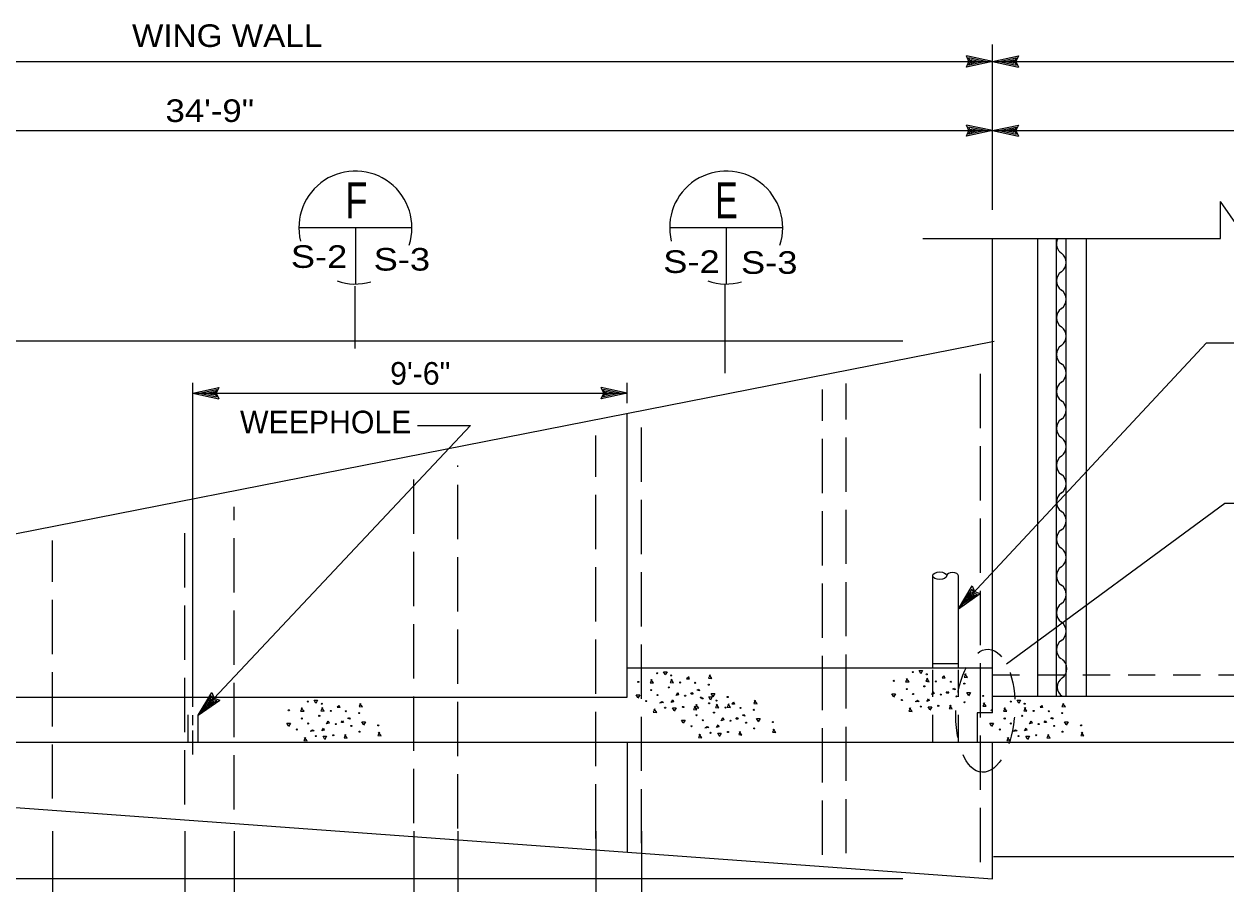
# Model space of a CAD drawing. Extents: x -22.3 to 19.7, y -11.8 to 18.2.
# Drawn here: x -13.77 to -7.13, y 1.6 to 6.36 of the extents above; entities that cross this region are included whole.
import ezdxf
from ezdxf.enums import TextEntityAlignment as Align

# ---------------------------------------------------------------- set-up
doc = ezdxf.new("R2010")
doc.units = 0
doc.header["$LTSCALE"] = 0.05
doc.linetypes.add('LONG_DASHED', pattern=[7.5, 6, -1.5])
doc.linetypes.add('MEDIUM_DASHED', pattern=[4.5, 3, -1.5])
doc.layers.add('1', color=7, linetype='Continuous', lineweight=13)
doc.layers.add('2', color=7, linetype='Continuous', lineweight=13)

msp = doc.modelspace()

# ---------------------------------------------------------------- linework, layer by layer
at = {"layer": '1'}
for p, q in [((-8.42042, 5.32831), (-8.42042, 6.24331)), ((-17.08742, 6.14831), (-8.42042, 6.14831)), ((-8.42042, 6.14831), (-8.56442, 6.17931)), ((-8.42042, 6.14831), (-8.56442, 6.11731)), ((-8.45742, 6.14831), (-8.55142, 6.16831)), ((-8.54242, 6.14831), (-8.55142, 6.16831)), ((-8.45742, 6.14831), (-8.55142, 6.12831)), ((-8.55142, 6.12831), (-8.54242, 6.14831)), ((-8.49342, 6.14831), (-8.53842, 6.15731)), ((-8.53442, 6.14831), (-8.53842, 6.15731)), ((-8.49342, 6.14831), (-8.53842, 6.13831)), ((-8.53842, 6.13831), (-8.53442, 6.14831)), ((-8.42042, 6.14831), (-8.27642, 6.17931)), ((-8.42042, 6.14831), (-1.02142, 6.14831)), ((-8.42042, 6.14831), (-8.27642, 6.11731)), ((-8.38342, 6.14831), (-8.28942, 6.16831)), ((-8.38342, 6.14831), (-8.28942, 6.12831)), ((-8.34742, 6.14831), (-8.30242, 6.15831)), ((-8.34742, 6.14831), (-8.30242, 6.13931)), ((-8.30242, 6.15831), (-8.30642, 6.14831)), ((-8.30642, 6.14831), (-8.30242, 6.13931)), ((-8.28942, 6.16831), (-8.29842, 6.14831)), ((-8.29842, 6.14831), (-8.28942, 6.12831)), ((-8.42042, 5.76631), (-8.56442, 5.79731)), ((-8.45742, 5.76631), (-8.55142, 5.78631)), ((-8.54242, 5.76631), (-8.55142, 5.78631)), ((-8.42042, 5.76631), (-8.27642, 5.79731)), ((-8.38342, 5.76631), (-8.28942, 5.78631)), ((-8.28942, 5.78631), (-8.29842, 5.76631)), ((-17.08742, 5.76631), (-8.42042, 5.76631)), ((-8.42042, 5.76631), (-8.56442, 5.73531)), ((-8.45742, 5.76631), (-8.55142, 5.74631)), ((-8.55142, 5.74631), (-8.54242, 5.76631)), ((-8.49342, 5.76631), (-8.53842, 5.77531)), ((-8.53442, 5.76631), (-8.53842, 5.77531)), ((-8.49342, 5.76631), (-8.53842, 5.75631)), ((-8.53842, 5.75631), (-8.53442, 5.76631)), ((-8.42042, 5.76631), (-8.27642, 5.73531)), ((-8.38342, 5.76631), (-8.28942, 5.74631)), ((-8.34742, 5.76631), (-8.30242, 5.77631)), ((-8.34742, 5.76631), (-8.30242, 5.75731)), ((-8.30242, 5.77631), (-8.30642, 5.76631)), ((-8.30642, 5.76631), (-8.30242, 5.75731)), ((-8.29842, 5.76631), (-8.28942, 5.74631)), ((-7.15942, 5.16931), (-7.15942, 5.37531)), ((-6.87442, 4.96231), (-7.15942, 5.37531)), ((-8.80542, 5.16931), (-7.15942, 5.16931)), ((-8.91642, 4.60131), (-18.84342, 4.60131)), ((-12.84142, 2.57831), (-12.84142, 4.37131)), ((-12.84142, 4.31431), (-12.69742, 4.34531)), ((-12.80442, 4.31431), (-12.71042, 4.33431)), ((-12.76842, 4.31431), (-12.72342, 4.32431)), ((-12.72342, 4.32431), (-12.72742, 4.31431)), ((-12.71042, 4.33431), (-12.71942, 4.31431)), ((-10.43942, 4.31431), (-10.58342, 4.34531)), ((-10.47642, 4.31431), (-10.57042, 4.33431)), ((-10.56142, 4.31431), (-10.57042, 4.33431)), ((-10.51242, 4.31431), (-10.55742, 4.32331)), ((-10.55342, 4.31431), (-10.55742, 4.32331)), ((-10.43942, 4.25831), (-10.43942, 4.37131)), ((-12.84142, 4.31431), (-10.43942, 4.31431)), ((-12.84142, 4.31431), (-12.69742, 4.28331)), ((-12.80442, 4.31431), (-12.71042, 4.29431)), ((-12.76842, 4.31431), (-12.72342, 4.30531)), ((-12.72742, 4.31431), (-12.72342, 4.30531)), ((-12.71942, 4.31431), (-12.71042, 4.29431)), ((-10.43942, 4.31431), (-10.58342, 4.28331)), ((-10.47642, 4.31431), (-10.57042, 4.29431)), ((-10.57042, 4.29431), (-10.56142, 4.31431)), ((-10.51242, 4.31431), (-10.55742, 4.30431)), ((-10.55742, 4.30431), (-10.55342, 4.31431)), ((-8.60842, 3.12131), (-8.53342, 3.24831)), ((-8.60842, 3.12131), (-8.48742, 3.20531)), ((-8.58342, 3.14831), (-8.53342, 3.23031)), ((-8.58342, 3.14831), (-8.50442, 3.20331)), ((-8.55842, 3.17431), (-8.53542, 3.21431)), ((-8.55842, 3.17431), (-8.52142, 3.20131)), ((-8.53542, 3.21431), (-8.53042, 3.20431)), ((-8.53342, 3.23031), (-8.52542, 3.21031)), ((-8.53042, 3.20431), (-8.52142, 3.20131)), ((-8.52542, 3.21031), (-8.50442, 3.20331)), ((-12.81242, 2.53231), (-12.69142, 2.61631)), ((-12.78742, 2.55931), (-12.73742, 2.64131)), ((-12.78742, 2.55931), (-12.70842, 2.61431)), ((-12.76242, 2.58531), (-12.73842, 2.62531)), ((-12.76242, 2.58531), (-12.72542, 2.61231)), ((-12.73842, 2.62531), (-12.73442, 2.61531)), ((-12.73742, 2.64131), (-12.72842, 2.62131)), ((-12.73442, 2.61531), (-12.72542, 2.61231)), ((-12.72842, 2.62131), (-12.70842, 2.61431)), ((-12.84142, 2.47831), (-12.84142, 2.53231)), ((-12.84142, 2.31531), (-12.84142, 2.44831)), ((-13.61742, 1.89131), (-13.61742, 0.62531)), ((-12.88542, 1.89131), (-12.88542, 0.62531)), ((-12.61342, 1.89131), (-12.61342, 0.62531)), ((-11.61942, 1.89131), (-11.61942, 0.62531)), ((-11.37642, 1.89131), (-11.37642, 0.62531)), ((-10.61342, 1.89131), (-10.61342, 0.62531)), ((-10.36042, 1.89131), (-10.36042, 0.62531)), ((-8.91642, 1.62731), (-18.86742, 1.62731))]:
    msp.add_line(p, q, dxfattribs=at)
at = {"layer": '1', "lineweight": 25}
for p, q in [((-8.42042, 2.54631), (-8.42042, 5.16931)), ((-8.17042, 2.63731), (-8.17042, 5.16931)), ((-8.06642, 2.63731), (-8.06642, 5.16931)), ((-8.01242, 2.63731), (-8.01242, 5.16931)), ((-7.90042, 2.63731), (-7.90042, 5.16931)), ((-10.43942, 2.63231), (-10.43942, 4.20231)), ((-8.75042, 2.79431), (-8.75042, 3.30431)), ((-8.60842, 2.79431), (-8.60842, 3.30431)), ((-10.43742, 2.79431), (-8.42042, 2.79431)), ((-8.75042, 2.81831), (-8.60842, 2.81831)), ((-17.08742, 2.63231), (-10.43942, 2.63231)), ((-8.42042, 2.63731), (-1.02142, 2.63731)), ((-8.42042, 2.54631), (-8.50542, 2.54631)), ((-8.50542, 2.54631), (-8.50542, 2.38431)), ((-17.08742, 2.38431), (-6.38842, 2.38431)), ((-10.43942, 2.38431), (-10.43942, 1.77531)), ((-8.42042, 1.62731), (-8.42042, 2.38431)), ((-17.08742, 2.26031), (-8.42042, 1.62731)), ((-8.41542, 1.75131), (-6.21842, 1.75131))]:
    msp.add_line(p, q, dxfattribs=at)
at = {"layer": '1', "linetype": 'LONG_DASHED', "lineweight": 25}
for p, q in [((-8.48642, 1.72031), (-8.48642, 4.51931)), ((-9.35942, 1.76131), (-9.35942, 4.33431)), ((-9.22942, 1.76931), (-9.22942, 4.36731)), ((-10.36042, 1.82431), (-10.36042, 4.13131)), ((-10.61342, 1.85131), (-10.61342, 4.07931)), ((-11.61942, 1.93631), (-11.61942, 3.89231)), ((-11.37642, 1.90631), (-11.37642, 3.91331)), ((-12.61342, 2.01131), (-12.61342, 3.68531)), ((-12.88542, 2.03931), (-12.88542, 3.63031)), ((-13.61742, 2.07131), (-13.61742, 3.49931))]:
    msp.add_line(p, q, dxfattribs=at)
at = {"layer": '1', "linetype": 'MEDIUM_DASHED'}
for p, q in [((-8.75042, 2.38431), (-8.75042, 2.79431)), ((-8.60842, 2.38431), (-8.60842, 2.79431)), ((-8.42042, 2.75631), (-1.02142, 2.75631)), ((-12.86642, 2.38431), (-12.86642, 2.63231)), ((-12.81242, 2.38431), (-12.81242, 2.63231))]:
    msp.add_line(p, q, dxfattribs=at)
at = {"layer": '1'}
for points in [[(-8.56442, 6.11731), (-8.55042, 6.14831), (-8.56442, 6.17931)], [(-8.27642, 6.17931), (-8.29042, 6.14831), (-8.27642, 6.11731)], [(-8.56442, 5.73531), (-8.55042, 5.76631), (-8.56442, 5.79731)], [(-8.27642, 5.79731), (-8.29042, 5.76631), (-8.27642, 5.73531)], [(-8.42042, 5.76631), (-4.72742, 5.76631), (-1.02142, 5.76631)], [(-8.60842, 3.12131), (-7.23742, 4.59331), (-6.63942, 4.59331)], [(-12.69742, 4.34531), (-12.71142, 4.31431), (-12.69742, 4.28331)], [(-10.58342, 4.28331), (-10.56942, 4.31431), (-10.58342, 4.34531)], [(-11.59942, 4.13531), (-11.30642, 4.13531), (-12.81242, 2.53231), (-12.73642, 2.65831)], [(-8.53342, 3.24831), (-8.51942, 3.21631), (-8.48742, 3.20531)], [(-12.73642, 2.65831), (-12.72342, 2.62731), (-12.69142, 2.61631)]]:
    msp.add_lwpolyline(points, dxfattribs=at)
at = {"layer": '1', "lineweight": 25}
for points in [[(-17.08742, 2.26031), (-17.08742, 2.89431), (-8.41142, 4.60231)], [(-8.34342, 2.81631), (-7.13542, 3.70631), (-6.95242, 3.70631)]]:
    msp.add_lwpolyline(points, dxfattribs=at)
for centre, start, end in [((-8.00492, 5.13931), 152.03288, 235.92281), ((-8.07392, 5.03731), 304.0772, 55.92281), ((-8.00492, 4.93531), 124.0772, 235.92281), ((-8.07392, 4.83331), 304.0772, 55.92281), ((-8.00492, 4.73131), 124.0772, 235.92281), ((-8.07392, 4.62931), 304.0772, 55.92281), ((-8.00492, 4.52731), 124.0772, 235.92281), ((-8.07392, 4.42531), 304.0772, 55.92281), ((-8.00492, 4.32331), 124.0772, 235.92281), ((-8.07392, 4.22131), 304.0772, 55.92281), ((-8.00492, 4.11931), 124.0772, 235.92281), ((-8.07392, 4.01731), 304.0772, 55.92281), ((-8.00492, 3.91531), 124.0772, 235.92281), ((-8.07392, 3.81331), 304.0772, 55.92281), ((-8.00492, 3.71131), 124.0772, 235.92281), ((-8.07392, 3.60931), 304.0772, 55.92281), ((-8.00492, 3.50731), 124.0772, 235.92281), ((-8.07392, 3.40531), 304.0772, 55.92281), ((-8.00492, 3.30331), 124.0772, 235.92281), ((-8.07392, 3.20131), 304.0772, 55.92281), ((-8.00492, 3.09931), 124.0772, 235.92281), ((-8.07392, 2.99731), 304.0772, 55.92281), ((-8.00492, 2.89531), 124.0772, 235.92281), ((-8.06992, 2.79031), 304.0772, 55.92281), ((-8.00092, 2.68831), 124.0772, 235.92281)]:
    msp.add_arc(centre, 0.06157, start, end, dxfattribs=at)
msp.add_ellipse((-8.71192, 3.30431), major_axis=(0.0385, 0), ratio=0.545501, dxfattribs=at)
msp.add_ellipse((-8.64092, 3.30431), major_axis=(-0.0325, 0), ratio=0.528164, start_param=3.1415927, end_param=6.2831853, dxfattribs=at)
at = {"layer": '1', "linetype": 'MEDIUM_DASHED', "lineweight": 25}
msp.add_ellipse((-8.45942, 2.55731), major_axis=(-0.018, -0.34), ratio=0.477924, dxfattribs=at)
at = {"layer": '2', "lineweight": 25}
for p, q in [((-12.25442, 5.23031), (-11.63042, 5.23031)), ((-11.94242, 5.23031), (-11.94242, 4.91831)), ((-10.20442, 5.23031), (-9.58042, 5.23031)), ((-9.89242, 5.23031), (-9.89242, 4.91831)), ((-11.94342, 4.56131), (-11.94342, 4.90631)), ((-9.89842, 4.42531), (-9.89842, 4.91631))]:
    msp.add_line(p, q, dxfattribs=at)
at = {"layer": '2'}
for p, q in [((-10.11142, 2.73531), (-10.10142, 2.74431)), ((-8.69842, 2.74131), (-8.68842, 2.75031)), ((-9.86142, 2.59631), (-9.85142, 2.60531)), ((-12.04342, 2.57831), (-12.03342, 2.58731)), ((-8.15742, 2.57831), (-8.14742, 2.58731))]:
    msp.add_line(p, q, dxfattribs=at)
for points in [[(-10.30442, 2.73031), (-10.31342, 2.71231), (-10.29442, 2.71131), (-10.30942, 2.73031)], [(-10.22942, 2.75731), (-10.23842, 2.77331), (-10.21942, 2.77331), (-10.22942, 2.75531)], [(-10.19242, 2.73231), (-10.20142, 2.71431), (-10.18342, 2.71231), (-10.19642, 2.73231)], [(-10.10142, 2.74631), (-10.09742, 2.73231), (-10.11142, 2.73231)], [(-9.98142, 2.75531), (-9.99042, 2.73731), (-9.97142, 2.73531), (-9.98542, 2.75531)], [(-8.89142, 2.73631), (-8.90042, 2.71831), (-8.88142, 2.71731), (-8.89642, 2.73631)], [(-8.81642, 2.76331), (-8.82542, 2.77931), (-8.80642, 2.77931), (-8.81642, 2.76131)], [(-8.77942, 2.73831), (-8.78842, 2.72031), (-8.77042, 2.71831), (-8.78342, 2.73831)], [(-8.68842, 2.75231), (-8.68442, 2.73831), (-8.69842, 2.73831)], [(-8.56842, 2.76131), (-8.57742, 2.74331), (-8.55842, 2.74131), (-8.57242, 2.76131)], [(-10.08842, 2.64931), (-10.08242, 2.65831), (-10.07542, 2.64931), (-10.08642, 2.64931)], [(-10.05242, 2.67331), (-10.04342, 2.67631), (-10.03942, 2.66731), (-10.05242, 2.67131)], [(-8.67542, 2.65531), (-8.66942, 2.66431), (-8.66242, 2.65531), (-8.67342, 2.65531)], [(-8.63942, 2.67931), (-8.63042, 2.68231), (-8.62642, 2.67331), (-8.63942, 2.67731)], [(-8.55342, 2.64431), (-8.56242, 2.65931), (-8.54242, 2.65931), (-8.55342, 2.64031)], [(-12.16142, 2.60031), (-12.17042, 2.61631), (-12.15142, 2.61631), (-12.16142, 2.59831)], [(-11.91342, 2.59831), (-11.92242, 2.58031), (-11.90342, 2.57831), (-11.91742, 2.59831)], [(-10.38042, 2.63031), (-10.38942, 2.64531), (-10.36942, 2.64531), (-10.38042, 2.62731)], [(-10.25642, 2.60331), (-10.24742, 2.60931), (-10.23842, 2.60331), (-10.26042, 2.60031)], [(-9.97942, 2.61831), (-9.98842, 2.63431), (-9.96942, 2.63431), (-9.97942, 2.61631)], [(-9.96642, 2.63831), (-9.97542, 2.65331), (-9.95542, 2.65331), (-9.96642, 2.63431)], [(-9.94242, 2.59331), (-9.95142, 2.57531), (-9.93342, 2.57331), (-9.94642, 2.59331)], [(-9.87742, 2.59531), (-9.88642, 2.57731), (-9.86842, 2.57631), (-9.88242, 2.59531)], [(-9.85142, 2.60731), (-9.84742, 2.59331), (-9.86142, 2.59331)], [(-9.73142, 2.61631), (-9.74042, 2.59831), (-9.72142, 2.59631), (-9.73542, 2.61631)], [(-8.96742, 2.63631), (-8.97642, 2.65131), (-8.95642, 2.65131), (-8.96742, 2.63331)], [(-8.84342, 2.60931), (-8.83442, 2.61531), (-8.82542, 2.60931), (-8.84742, 2.60631)], [(-8.46442, 2.60131), (-8.47342, 2.58331), (-8.45542, 2.58231), (-8.46942, 2.60131)], [(-8.27542, 2.60031), (-8.28442, 2.61631), (-8.26542, 2.61631), (-8.27542, 2.59831)], [(-8.02742, 2.59831), (-8.03642, 2.58031), (-8.01742, 2.57831), (-8.03142, 2.59831)], [(-12.23642, 2.57331), (-12.24542, 2.55531), (-12.22642, 2.55431), (-12.24142, 2.57331)], [(-12.12442, 2.57531), (-12.13342, 2.55731), (-12.11542, 2.55531), (-12.12842, 2.57531)], [(-12.03342, 2.58931), (-12.02942, 2.57531), (-12.04342, 2.57531)], [(-10.28642, 2.56731), (-10.29542, 2.54931), (-10.27642, 2.54731), (-10.29142, 2.56731)], [(-10.18042, 2.55831), (-10.18942, 2.57331), (-10.16942, 2.57331), (-10.18042, 2.55431)], [(-10.06442, 2.58231), (-10.07342, 2.56431), (-10.05542, 2.56231), (-10.06842, 2.58231)], [(-10.05442, 2.59131), (-10.06342, 2.57331), (-10.04442, 2.57231), (-10.05942, 2.59131)], [(-9.80242, 2.53431), (-9.79342, 2.53731), (-9.78942, 2.52831), (-9.80242, 2.53231)], [(-8.87342, 2.57331), (-8.88242, 2.55531), (-8.86342, 2.55331), (-8.87842, 2.57331)], [(-8.76742, 2.56431), (-8.77642, 2.57931), (-8.75642, 2.57931), (-8.76742, 2.56031)], [(-8.65142, 2.58831), (-8.66042, 2.57031), (-8.64242, 2.56831), (-8.65542, 2.58831)], [(-8.35042, 2.57331), (-8.35942, 2.55531), (-8.34042, 2.55431), (-8.35542, 2.57331)], [(-8.23842, 2.57531), (-8.24742, 2.55731), (-8.22942, 2.55531), (-8.24242, 2.57531)], [(-8.14742, 2.58931), (-8.14342, 2.57531), (-8.15742, 2.57531)], [(-12.31242, 2.47331), (-12.32142, 2.48831), (-12.30142, 2.48831), (-12.31242, 2.47031)], [(-12.02042, 2.49231), (-12.01442, 2.50131), (-12.00742, 2.49231), (-12.01842, 2.49231)], [(-11.98442, 2.51631), (-11.97542, 2.51931), (-11.97142, 2.51031), (-11.98442, 2.51431)], [(-11.89842, 2.48131), (-11.90742, 2.49631), (-11.88742, 2.49631), (-11.89842, 2.47731)], [(-10.13042, 2.49131), (-10.13942, 2.50631), (-10.11942, 2.50631), (-10.13042, 2.48831)], [(-10.00642, 2.46431), (-9.99742, 2.47031), (-9.98842, 2.46431), (-10.01042, 2.46131)], [(-9.83842, 2.51031), (-9.83242, 2.51931), (-9.82542, 2.51031), (-9.83642, 2.51031)], [(-9.71642, 2.49931), (-9.72542, 2.51431), (-9.70542, 2.51431), (-9.71642, 2.49531)], [(-8.42642, 2.47331), (-8.43542, 2.48831), (-8.41542, 2.48831), (-8.42642, 2.47031)], [(-8.13442, 2.49231), (-8.12842, 2.50131), (-8.12142, 2.49231), (-8.13242, 2.49231)], [(-8.09842, 2.51631), (-8.08942, 2.51931), (-8.08542, 2.51031), (-8.09842, 2.51431)], [(-8.01242, 2.48131), (-8.02142, 2.49631), (-8.00142, 2.49631), (-8.01242, 2.47731)], [(-12.21842, 2.41031), (-12.22742, 2.39231), (-12.20842, 2.39031), (-12.22342, 2.41031)], [(-12.18842, 2.44631), (-12.17942, 2.45231), (-12.17042, 2.44631), (-12.19242, 2.44331)], [(-12.11242, 2.40131), (-12.12142, 2.41631), (-12.10142, 2.41631), (-12.11242, 2.39731)], [(-11.99642, 2.42531), (-12.00542, 2.40731), (-11.98742, 2.40531), (-12.00042, 2.42531)], [(-11.80942, 2.43831), (-11.81842, 2.42031), (-11.80042, 2.41931), (-11.81442, 2.43831)], [(-10.03642, 2.42831), (-10.04542, 2.41031), (-10.02642, 2.40831), (-10.04142, 2.42831)], [(-9.93042, 2.41931), (-9.93942, 2.43431), (-9.91942, 2.43431), (-9.93042, 2.41531)], [(-9.81442, 2.44331), (-9.82342, 2.42531), (-9.80542, 2.42331), (-9.81842, 2.44331)], [(-9.62742, 2.45631), (-9.63642, 2.43831), (-9.61842, 2.43731), (-9.63242, 2.45631)], [(-8.33242, 2.41031), (-8.34142, 2.39231), (-8.32242, 2.39031), (-8.33742, 2.41031)], [(-8.30242, 2.44631), (-8.29342, 2.45231), (-8.28442, 2.44631), (-8.30642, 2.44331)], [(-8.22642, 2.40131), (-8.23542, 2.41631), (-8.21542, 2.41631), (-8.22642, 2.39731)], [(-8.11042, 2.42531), (-8.11942, 2.40731), (-8.10142, 2.40531), (-8.11442, 2.42531)], [(-7.92342, 2.43831), (-7.93242, 2.42031), (-7.91442, 2.41931), (-7.92842, 2.43831)]]:
    msp.add_lwpolyline(points, dxfattribs=at)
for points in [[(-10.16942, 2.64131), (-10.16042, 2.65831), (-10.15542, 2.64631)], [(-8.75642, 2.64731), (-8.74742, 2.66431), (-8.74242, 2.65231)], [(-10.19642, 2.60331), (-10.18742, 2.61831), (-10.18342, 2.60731)], [(-8.78342, 2.60931), (-8.77442, 2.62431), (-8.77042, 2.61331)], [(-12.12842, 2.44631), (-12.11942, 2.46131), (-12.11542, 2.45031)], [(-12.10142, 2.48431), (-12.09242, 2.50131), (-12.08742, 2.48931)], [(-9.94642, 2.46431), (-9.93742, 2.47931), (-9.93342, 2.46831)], [(-9.91942, 2.50231), (-9.91042, 2.51931), (-9.90542, 2.50731)], [(-8.24242, 2.44631), (-8.23342, 2.46131), (-8.22942, 2.45031)], [(-8.21542, 2.48431), (-8.20642, 2.50131), (-8.20142, 2.48931)]]:
    msp.add_lwpolyline(points, close=True, dxfattribs=at)
for centre in [(-10.27347, 2.76514), (-10.19652, 2.75299), (-8.96532, 2.72299), (-8.86047, 2.77114), (-8.78352, 2.75899), (-10.37832, 2.71699), (-10.30677, 2.67154), (-10.21002, 2.68639), (-10.14657, 2.71384), (-10.06332, 2.71204), (-9.98907, 2.70169), (-8.89377, 2.67754), (-8.79702, 2.69239), (-8.73357, 2.71984), (-8.65032, 2.71804), (-8.57607, 2.70769), (-12.20547, 2.60814), (-12.12852, 2.59599), (-10.33422, 2.61079), (-10.27212, 2.64409), (-10.11912, 2.64094), (-10.03272, 2.63059), (-10.02347, 2.62614), (-9.98727, 2.59864), (-9.94652, 2.61399), (-9.88422, 2.63374), (-8.92122, 2.61679), (-8.85912, 2.65009), (-8.70612, 2.64694), (-8.61972, 2.63659), (-8.57427, 2.60464), (-8.47122, 2.63974), (-8.31947, 2.60814), (-8.24252, 2.59599), (-12.31032, 2.55999), (-12.14202, 2.52939), (-12.07857, 2.55684), (-11.99532, 2.55504), (-11.92107, 2.54469), (-10.22982, 2.57434), (-10.13262, 2.57884), (-10.12832, 2.57799), (-10.05677, 2.53254), (-9.96002, 2.54739), (-9.89657, 2.57484), (-9.81332, 2.57304), (-9.73907, 2.56269), (-8.81682, 2.58034), (-8.71962, 2.58484), (-8.42432, 2.55999), (-8.25602, 2.52939), (-8.19257, 2.55684), (-8.10932, 2.55504), (-8.03507, 2.54469), (-12.23877, 2.51454), (-12.20412, 2.48709), (-12.05112, 2.48394), (-11.96472, 2.47359), (-11.81622, 2.47674), (-10.08422, 2.47179), (-10.02212, 2.50509), (-9.86912, 2.50194), (-9.78272, 2.49159), (-9.73727, 2.45964), (-9.63422, 2.49474), (-8.35277, 2.51454), (-8.31812, 2.48709), (-8.16512, 2.48394), (-8.07872, 2.47359), (-7.93022, 2.47674), (-12.26622, 2.45379), (-12.16182, 2.41734), (-12.06462, 2.42184), (-11.91927, 2.44164), (-9.97982, 2.43534), (-9.88262, 2.43984), (-8.38022, 2.45379), (-8.27582, 2.41734), (-8.17862, 2.42184), (-8.03327, 2.44164)]:
    msp.add_circle(centre, 0.00293, dxfattribs=at)
at = {"layer": '2', "lineweight": 25}
for centre, start, end in [((-11.94242, 5.23031), 341.96976, 193.81208), ((-9.89242, 5.23031), 341.96976, 193.81208), ((-11.94242, 5.23031), 251.04049, 285.74671), ((-9.89242, 5.23031), 251.04049, 285.74671)]:
    msp.add_arc(centre, 0.3125, start, end, dxfattribs=at)

# ---------------------------------------------------------------- texts
at = {"layer": '1'}
for s, width, p in [('WING WALL', 1.1, (-12.65142, 6.22931)), ('34\'-9"', 1.15, (-12.74742, 5.81431))]:
    msp.add_text(s, height=0.125, dxfattribs=dict(at, width=width)).set_placement(p, align=Align.CENTER)
msp.add_text('9\'-6"', height=0.125, dxfattribs=at).set_placement((-11.58392, 4.36131), align=Align.CENTER)
msp.add_text('WEEPHOLE', height=0.125, dxfattribs=at).set_placement((-12.58042, 4.09231))
at = {"layer": '2'}
for s, height, width, p in [('F', 0.2, 0.75, (-11.93742, 5.28131)), ('E', 0.2, 0.7, (-9.89142, 5.28131)), ('S-2', 0.125, 1.2, (-12.14342, 5.00731)), ('S-3', 0.125, 1.2, (-11.68542, 4.99231)), ('S-2', 0.125, 1.2, (-10.08442, 4.97931)), ('S-3', 0.125, 1.2, (-9.65442, 4.97431))]:
    msp.add_text(s, height=height, dxfattribs=dict(at, width=width)).set_placement(p, align=Align.CENTER)

doc.saveas('drawing.dxf')
